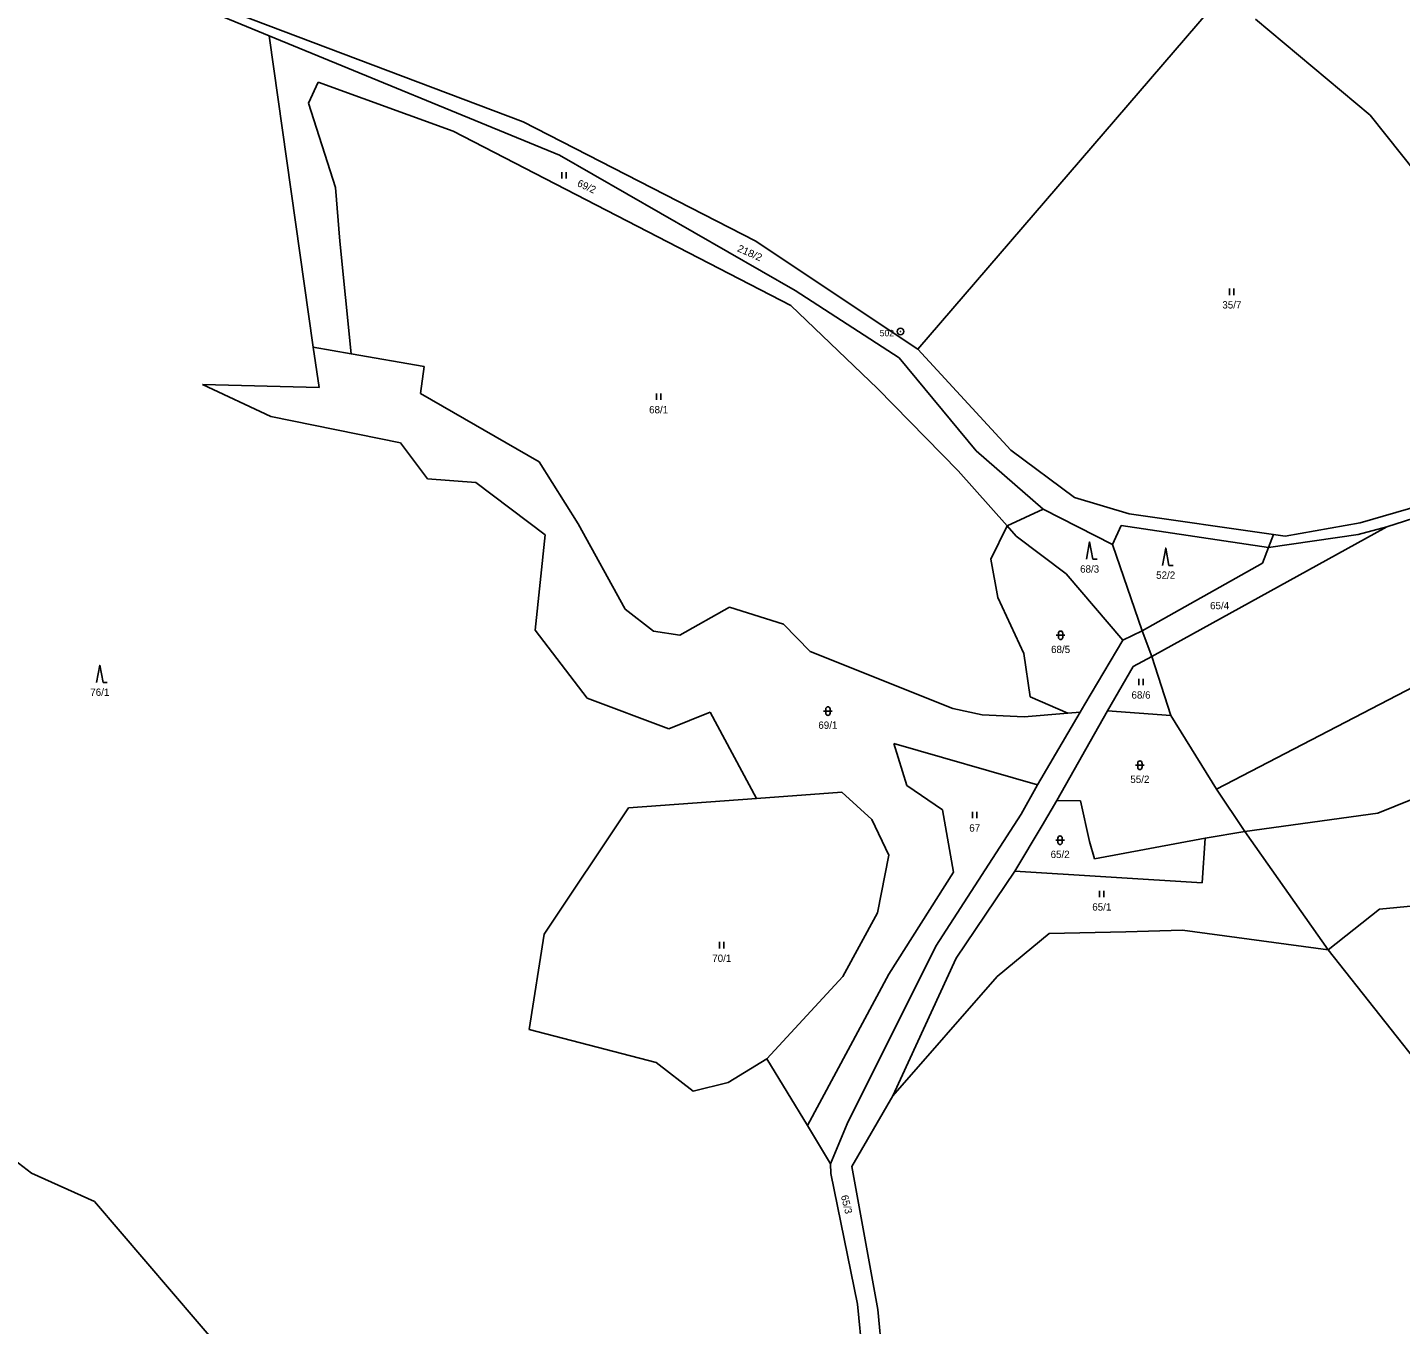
# Model space of a CAD drawing. Extents: x -601877 to -599786, y -1122905 to -1121218.
# Drawn here: x -600496.9 to -600177.9, y -1121972.1 to -1121670.7 of the extents above; entities that cross this region are included whole.
import ezdxf
from ezdxf.enums import TextEntityAlignment as Align

# ---------------------------------------------------------------- set-up
doc = ezdxf.new("R2010")
doc.units = 0
doc.header["$LTSCALE"] = 0.68
for name, color, linetype, lineweight in [('1', 7, 'Continuous', 25), ('3', 7, 'Continuous', 25), ('8', 7, 'Continuous', 25)]:
    doc.layers.add(name, color=color, linetype=linetype, lineweight=lineweight)
doc.layers.add('2', color=7, linetype='Continuous')

msp = doc.modelspace()

# ---------------------------------------------------------------- linework, layer by layer
at = {"layer": '1'}
for p, q in [((-600381.71, -1121692.64), (-600458.44, -1121663.63)), ((-600290.03, -1121745.45), (-600219.7, -1121663.67)), ((-600459.6, -1121664.93), (-600440.75, -1121672.67)), ((-600211.53, -1121668.75), (-600184.91, -1121691.09)), ((-600440.75, -1121672.67), (-600373.32, -1121700.37)), ((-600430.49, -1121745.02), (-600440.75, -1121672.67)), ((-600431.62, -1121688.28), (-600429.34, -1121683.44)), ((-600429.34, -1121683.44), (-600398, -1121694.84)), ((-600425.33, -1121707.88), (-600431.62, -1121688.28)), ((-600327.83, -1121720.28), (-600381.71, -1121692.64)), ((-600184.91, -1121691.09), (-600155.44, -1121728.29)), ((-600398, -1121694.84), (-600319.54, -1121735.33)), ((-600373.32, -1121700.37), (-600318.5, -1121731.84)), ((-600424.33, -1121720.37), (-600425.33, -1121707.88)), ((-600421.69, -1121746.54), (-600424.33, -1121720.37)), ((-600290.03, -1121745.45), (-600327.83, -1121720.28)), ((-600318.5, -1121731.84), (-600294.34, -1121747.47)), ((-600319.54, -1121735.33), (-600299.4, -1121754.57)), ((-600421.69, -1121746.54), (-600430.49, -1121745.02)), ((-600429.16, -1121754.38), (-600430.49, -1121745.02)), ((-600404.74, -1121749.46), (-600421.69, -1121746.54)), ((-600268.42, -1121768.97), (-600290.03, -1121745.45)), ((-600405.56, -1121755.75), (-600404.74, -1121749.46)), ((-600294.34, -1121747.47), (-600276.48, -1121769.08)), ((-600429.16, -1121754.38), (-600456.22, -1121753.65)), ((-600456.22, -1121753.65), (-600440.37, -1121761.13)), ((-600378.04, -1121771.62), (-600405.56, -1121755.75)), ((-600299.4, -1121754.57), (-600280.63, -1121773.71)), ((-600440.37, -1121761.13), (-600410.21, -1121767.24)), ((-600410.21, -1121767.24), (-600403.92, -1121775.63)), ((-600276.48, -1121769.08), (-600260.93, -1121782.64)), ((-600253.66, -1121779.91), (-600268.42, -1121768.97)), ((-600368.93, -1121786.02), (-600378.04, -1121771.62)), ((-600403.92, -1121775.63), (-600392.71, -1121776.45)), ((-600280.63, -1121773.71), (-600269.24, -1121786.48)), ((-600392.71, -1121776.45), (-600376.58, -1121788.58)), ((-600155.16, -1121776.54), (-600187.23, -1121785.84)), ((-600181.08, -1121786.75), (-600151.33, -1121777.18)), ((-600240.9, -1121783.74), (-600253.66, -1121779.91)), ((-600260.93, -1121782.64), (-600269.24, -1121786.48)), ((-600260.93, -1121782.64), (-600244.83, -1121790.86)), ((-600207.35, -1121788.55), (-600240.9, -1121783.74)), ((-600376.58, -1121788.58), (-600378.95, -1121810.73)), ((-600357.99, -1121805.9), (-600368.93, -1121786.02)), ((-600269.24, -1121786.48), (-600273.07, -1121794.23)), ((-600267.15, -1121788.94), (-600269.24, -1121786.48)), ((-600244.83, -1121790.86), (-600242.75, -1121786.47)), ((-600242.75, -1121786.47), (-600208.52, -1121791.52)), ((-600181.08, -1121786.75), (-600235.68, -1121816.9)), ((-600207.35, -1121788.55), (-600208.52, -1121791.52)), ((-600208.52, -1121791.52), (-600187.69, -1121788.55)), ((-600204.64, -1121788.94), (-600207.35, -1121788.55)), ((-600187.23, -1121785.84), (-600204.64, -1121788.94)), ((-600187.69, -1121788.55), (-600181.08, -1121786.75)), ((-600255.57, -1121797.7), (-600267.15, -1121788.94)), ((-600237.87, -1121810.88), (-600244.83, -1121790.86)), ((-600208.52, -1121791.52), (-600209.96, -1121795.16)), ((-600273.07, -1121794.23), (-600271.43, -1121803.17)), ((-600242.37, -1121813.12), (-600255.57, -1121797.7)), ((-600209.96, -1121795.16), (-600237.87, -1121810.88)), ((-600271.43, -1121803.17), (-600265.42, -1121816.21)), ((-600351.43, -1121811.01), (-600357.99, -1121805.9)), ((-600333.76, -1121805.45), (-600345.33, -1121811.92)), ((-600321.27, -1121809.37), (-600333.76, -1121805.45)), ((-600378.95, -1121810.73), (-600366.83, -1121826.6)), ((-600315.08, -1121815.75), (-600321.27, -1121809.37)), ((-600237.87, -1121810.88), (-600242.37, -1121813.12)), ((-600235.68, -1121816.9), (-600237.87, -1121810.88)), ((-600345.33, -1121811.92), (-600351.43, -1121811.01)), ((-600242.37, -1121813.12), (-600251.23, -1121827.96)), ((-600220.66, -1121847.71), (-600155.89, -1121814.11)), ((-600281.91, -1121828.97), (-600315.08, -1121815.75)), ((-600265.42, -1121816.21), (-600263.96, -1121826.24)), ((-600235.68, -1121816.9), (-600240, -1121819.24)), ((-600231.25, -1121830.57), (-600235.68, -1121816.9)), ((-600240, -1121819.24), (-600245.96, -1121829.52)), ((-600366.83, -1121826.6), (-600347.88, -1121833.71)), ((-600263.96, -1121826.24), (-600255.16, -1121830.07)), ((-600347.88, -1121833.71), (-600338.31, -1121829.79)), ((-600338.31, -1121829.79), (-600327.54, -1121849.85)), ((-600275.07, -1121830.43), (-600281.91, -1121828.97)), ((-600255.16, -1121830.07), (-600265.32, -1121830.89)), ((-600252.33, -1121829.84), (-600262.21, -1121846.74)), ((-600245.96, -1121829.52), (-600257.7, -1121850.38)), ((-600252.33, -1121829.84), (-600255.16, -1121830.07)), ((-600251.23, -1121827.96), (-600252.33, -1121829.84)), ((-600245.96, -1121829.52), (-600231.25, -1121830.57)), ((-600265.32, -1121830.89), (-600275.07, -1121830.43)), ((-600231.25, -1121830.57), (-600220.66, -1121847.71)), ((-600295.58, -1121837.09), (-600292.57, -1121846.84)), ((-600262.21, -1121846.74), (-600295.58, -1121837.09)), ((-600183.13, -1121853.27), (-600159.75, -1121843.89)), ((-600327.54, -1121849.85), (-600307.7, -1121848.39)), ((-600307.7, -1121848.39), (-600300.68, -1121854.78)), ((-600292.57, -1121846.84), (-600284.28, -1121852.5)), ((-600262.21, -1121846.74), (-600266.03, -1121853.48)), ((-600220.66, -1121847.71), (-600214.03, -1121857.58)), ((-600376.86, -1121881.4), (-600357.27, -1121852.04)), ((-600357.27, -1121852.04), (-600327.54, -1121849.85)), ((-600257.7, -1121850.38), (-600261.13, -1121856.14)), ((-600252.23, -1121850.41), (-600257.7, -1121850.38)), ((-600250.15, -1121859.84), (-600252.23, -1121850.41)), ((-600300.68, -1121854.78), (-600296.76, -1121863.07)), ((-600284.28, -1121852.5), (-600281.73, -1121866.99)), ((-600266.03, -1121853.48), (-600278.46, -1121872.81)), ((-600214.03, -1121857.58), (-600183.13, -1121853.27)), ((-600261.13, -1121856.14), (-600267.51, -1121866.77)), ((-600214.03, -1121857.58), (-600223.27, -1121859.13)), ((-600194.67, -1121885.03), (-600214.03, -1121857.58)), ((-600248.95, -1121863.92), (-600250.15, -1121859.84)), ((-600223.27, -1121859.13), (-600248.95, -1121863.92)), ((-600223.96, -1121869.45), (-600223.27, -1121859.13)), ((-600296.76, -1121863.07), (-600299.4, -1121876.48)), ((-600281.73, -1121866.99), (-600296.76, -1121890.7)), ((-600267.51, -1121866.77), (-600281.08, -1121886.98)), ((-600267.51, -1121866.77), (-600223.96, -1121869.45)), ((-600278.46, -1121872.81), (-600285.87, -1121884.18)), ((-600165.5, -1121873.94), (-600182.73, -1121875.57)), ((-600299.4, -1121876.48), (-600307.42, -1121891.25)), ((-600182.73, -1121875.57), (-600194.67, -1121885.03)), ((-600259.51, -1121881.27), (-600241.72, -1121880.83)), ((-600241.72, -1121880.83), (-600228.52, -1121880.46)), ((-600228.52, -1121880.46), (-600194.67, -1121885.03)), ((-600380.32, -1121903.56), (-600376.86, -1121881.4)), ((-600285.87, -1121884.18), (-600306.46, -1121925.47)), ((-600271.61, -1121891.25), (-600259.51, -1121881.27)), ((-600281.08, -1121886.98), (-600295.82, -1121918.97)), ((-600194.67, -1121885.03), (-600166.79, -1121920.41)), ((-600296.76, -1121890.7), (-600315.69, -1121925.86)), ((-600307.42, -1121891.25), (-600325.1, -1121910.4)), ((-600295.82, -1121918.97), (-600271.61, -1121891.25)), ((-600350.8, -1121911.22), (-600380.32, -1121903.56)), ((-600342.23, -1121917.87), (-600350.8, -1121911.22)), ((-600325.1, -1121910.4), (-600334.12, -1121915.87)), ((-600315.69, -1121925.86), (-600325.1, -1121910.4)), ((-600334.12, -1121915.87), (-600342.23, -1121917.87)), ((-600295.82, -1121918.97), (-600305.35, -1121935.38)), ((-600517.85, -1121920.16), (-600495.93, -1121936.94)), ((-600306.46, -1121925.47), (-600310.28, -1121934.75)), ((-600310.28, -1121934.75), (-600315.69, -1121925.86)), ((-600310.28, -1121934.75), (-600310.24, -1121937.05)), ((-600305.35, -1121935.38), (-600299.3, -1121968.61)), ((-600495.93, -1121936.94), (-600481.34, -1121943.53)), ((-600310.24, -1121937.05), (-600304.07, -1121967.38)), ((-600481.34, -1121943.53), (-600451.53, -1121978.39)), ((-600304.07, -1121967.38), (-600300.36, -1122005.74)), ((-600299.3, -1121968.61), (-600295.78, -1122007.91))]:
    msp.add_line(p, q, dxfattribs=at)
at = {"layer": '3'}
for p, q in [((-600372.751, -1121705.8), (-600372.751, -1121704.3)), ((-600371.75, -1121705.8), (-600371.75, -1121704.3)), ((-600217.571, -1121732.89), (-600217.571, -1121731.39)), ((-600216.57, -1121732.89), (-600216.57, -1121731.39)), ((-600350.761, -1121757.25), (-600350.761, -1121755.75)), ((-600349.76, -1121757.25), (-600349.76, -1121755.75)), ((-600249.36, -1121794.27), (-600248.364, -1121794.27)), ((-600231.69, -1121795.7), (-600230.694, -1121795.7)), ((-600257.851, -1121811.961), (-600255.849, -1121811.961)), ((-600257.351, -1121811.461), (-600257.351, -1121812.462)), ((-600256.349, -1121812.462), (-600256.349, -1121811.461)), ((-600479.35, -1121822.9), (-600478.354, -1121822.9)), ((-600238.681, -1121823.54), (-600238.681, -1121822.04)), ((-600237.68, -1121823.54), (-600237.68, -1121822.04)), ((-600311.931, -1121829.561), (-600309.929, -1121829.561)), ((-600311.431, -1121829.061), (-600311.431, -1121830.062)), ((-600310.429, -1121830.062), (-600310.429, -1121829.061)), ((-600239.441, -1121842.141), (-600237.439, -1121842.141)), ((-600238.941, -1121841.641), (-600238.941, -1121842.642)), ((-600237.939, -1121842.642), (-600237.939, -1121841.641)), ((-600277.321, -1121854.45), (-600277.321, -1121852.95)), ((-600276.32, -1121854.45), (-600276.32, -1121852.95)), ((-600257.961, -1121859.581), (-600255.959, -1121859.581)), ((-600257.461, -1121859.081), (-600257.461, -1121860.082)), ((-600256.459, -1121860.082), (-600256.459, -1121859.081)), ((-600247.791, -1121872.8), (-600247.791, -1121871.3)), ((-600246.79, -1121872.8), (-600246.79, -1121871.3)), ((-600336.091, -1121884.72), (-600336.091, -1121883.22)), ((-600335.09, -1121884.72), (-600335.09, -1121883.22))]:
    msp.add_line(p, q, dxfattribs=at)
for points in [[(-600249.36, -1121794.27), (-600250.11, -1121790.27), (-600250.86, -1121794.27)], [(-600231.69, -1121795.7), (-600232.44, -1121791.7), (-600233.19, -1121795.7)], [(-600479.35, -1121822.9), (-600480.1, -1121818.9), (-600480.85, -1121822.9)]]:
    msp.add_lwpolyline(points, dxfattribs=at)
for centre, start, end in [((-600256.85, -1121811.4609), 0, 180), ((-600256.85, -1121812.4609), 180, 359.98789), ((-600310.93, -1121829.0609), 0, 180), ((-600310.93, -1121830.0609), 180, 359.98789), ((-600238.44, -1121841.6409), 0, 180), ((-600238.44, -1121842.6409), 180, 359.98789), ((-600256.96, -1121859.0809), 0, 180), ((-600256.96, -1121860.0809), 180, 359.98789)]:
    msp.add_arc(centre, 0.5, start, end, dxfattribs=at)
at = {"layer": '8'}
for radius in [0.75, 0.03]:
    msp.add_circle((-600294.05, -1121741.3698), radius, dxfattribs=at)

# ---------------------------------------------------------------- texts
at = {"layer": '2'}
for s, rotation, p in [('69/2', 335, (-600367.3257, -1121708.4196)), ('65/3', 284, (-600307.3863, -1121944.3869))]:
    msp.add_text(s, height=1.7, rotation=rotation, dxfattribs=at).set_placement(p, align=Align.CENTER)
at = {"layer": '2', "width": 1.05}
msp.add_text('218/2', height=1.7, rotation=336, dxfattribs=at).set_placement((-600329.4057, -1121723.8661), align=Align.CENTER)
at = {"layer": '2'}
for s, p in [('35/7', (-600217.059, -1121736.015)), ('68/1', (-600350.249, -1121760.375)), ('68/3', (-600250.109, -1121797.395)), ('52/2', (-600232.439, -1121798.825)), ('65/4', (-600219.909, -1121805.895)), ('68/5', (-600256.849, -1121816.085)), ('76/1', (-600480.099, -1121826.025)), ('68/6', (-600238.169, -1121826.665)), ('69/1', (-600310.929, -1121833.685)), ('55/2', (-600238.439, -1121846.265)), ('67', (-600276.809, -1121857.575)), ('65/2', (-600256.959, -1121863.705)), ('65/1', (-600247.279, -1121875.925)), ('70/1', (-600335.579, -1121887.845))]:
    msp.add_text(s, height=1.7, dxfattribs=at).set_placement(p, align=Align.CENTER)
at = {"layer": '8'}
msp.add_text('502', height=1.5, dxfattribs=at).set_placement((-600295.549, -1121742.487), align=Align.RIGHT)

doc.saveas('drawing.dxf')
